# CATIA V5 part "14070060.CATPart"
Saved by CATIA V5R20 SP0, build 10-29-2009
Part number: 14070060
Definition: NONE
Nomenclature: 14070060
Source: Unknown
Description: 14070060
Bounding box of the stored display mesh (mm): x -30 to 120, y -49 to 39.1, z -39.1 to 39.1
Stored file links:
  C:\Users\Utente\Desktop\IO LAVORO\3D X SITO CF\X SITO\PLASTICA\RF2\14070060.CATPart
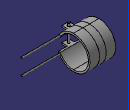
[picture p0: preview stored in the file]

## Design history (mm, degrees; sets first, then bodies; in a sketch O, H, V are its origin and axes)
Body1 "14070060" (main body)
  Solid1: solid without history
